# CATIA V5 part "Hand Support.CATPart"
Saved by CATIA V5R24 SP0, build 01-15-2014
Part number: Hand Support
Bounding box of the stored display mesh (mm): x -20 to 20, y -52.995 to 52.995, z -21 to 17
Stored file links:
  C:\Users\minsi\Google 드라이브\CDL_2019\00_CLASS\00_CAD\기말고사\DMU\Hand Support.CATPart
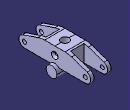
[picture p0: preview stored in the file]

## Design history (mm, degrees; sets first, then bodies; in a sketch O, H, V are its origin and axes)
Body1 (main body)
  Sketch1 on yz-plane, origin (0, 0, 0), H (0, 1, 0), V (0, 0, 1)
    point P1 (0, 17)
    line L1 (0, 17) -> (15.0143, 17)
    point P2 (20, 17)
    line L2 (24.7177, 15.3874) -> (47.5876, 7.57)
    point P3 (47.5876, 7.57)
    arc A1 centre (45, 0) radius 8 from (47.5876, 7.57) to (45, -8) cw
    point P4 (45, 0)
    point P5 (45, -8)
    line L3 (45, -8) -> (0, -8)
    point P6 (0, -8)
    arc A2 centre (15.0143, -13) radius 30 from (15.0143, 17) to (24.7177, 15.3874) cw
    point P7 (15.0143, 17)
    point P8 (24.7177, 15.3874)
    point P10 (0, -8)
    point P11 (-45, -8)
    line L4 (-45, -8) -> (0, -8)
    point P12 (-47.5876, 7.57)
    arc A3 centre (-45, 0) radius 8 from (-47.5876, 7.57) to (-45, -8) ccw
    point P14 (-24.7177, 15.3874)
    line L5 (-24.7177, 15.3874) -> (-47.5876, 7.57)
    point P15 (-15.0143, 17)
    arc A4 centre (-15.0143, -13) radius 30 from (-15.0143, 17) to (-24.7177, 15.3874) ccw
    point P17 (0, 17)
    line L6 (0, 17) -> (-15.0143, 17)
    radius A1 = 8
    distance L1 L3 = 25
    distance P4 V = 45
    distance P2 V = 20
    radius A2 = 30
    coincidence: P1 V, P6 V, P4 H, L1 P2, L2 P2, P1 P17, P6 P10
    horizontal: L1 H, L3 H
    tangency: A1 L2, L3 A1, A2 L1, A2 L2
    symmetry: P6 P10 V, P5 P11 V, L3 L4 V, P3 P12 V, A1 A3 V, P8 P14 V, L2 L5 V, P7 P15 V, A2 A4 V, P1 P17 V, L1 L6 V
  Pad1: profile Sketch1, direction (1, 0, 0), length 15, mirrored extent
  Sketch2 on end face of Pad1, origin (15, 44.3018, -2.6158), H (0, 1, 0), V (0, 0, 1)
    point P1 (0.6982, 2.6158)
    reference projected arc E1 centre (0.6982, 2.6158) radius 8 from (0.6982, -5.3842) to (3.2858, 10.1858) ccw from edge [face of Pad1 from Sketch1.A1 | end face of Pad1]
    concentricity: E1 P1
  Hole1: placed by Sketch2, at (15, 45, 0) direction (-1, 0, 0), diameter 6, through (limit type 3)
  Sketch3 on end face of Pad1, origin (15, -42.3739, 0.0291), H (0, 1, 0), V (0, 0, 1)
    point P1 (-2.6261, -0.0291)
    reference projected arc E1 centre (-2.6261, -0.0291) radius 8 from (-5.2137, 7.5409) to (-2.6261, -8.0291) ccw from edge [face of Pad1 from Sketch1.A3 | end face of Pad1]
    concentricity: E1 P1
  Hole2: placed by Sketch3, at (15, -45, 0) direction (-1, 0, 0), diameter 6, through (limit type 3)
  Sketch4 on yz-plane, origin (0, 0, 0), H (0, 1, 0), V (0, 0, 1)
    circle A1 centre (0, -13) radius 8
    point P1 (0, -13)
    radius A1 = 8
    distance P1 H = 13
    coincidence: P1 V
  Pad2: profile Sketch4, direction (1, 0, 0), length 20, mirrored extent
  Sketch5 on face of Pad1 from Sketch1.L1, origin (-1.3402, 2.5662, 17), H (1, 0, 0), V (0, 1, 0)
    point P1 (1.3402, -2.5662)
    reference intersected line E1 through (1.3402, 0) direction (0, 1) from yz-plane
    reference intersected line E2 through (0, -2.5662) direction (-1, 0) from zx-plane
    coincidence: P1 E1, P1 E2
  Hole3: placed by Sketch5, at (0, 0, 17) direction (0, 0, -1), diameter 12, depth 20
  Sketch6 on end face of Pad1, origin (15, 7.2087, 2.4362), H (0, 1, 0), V (0, 0, 1)
    point P1 (-7.2087, 2.5638)
    reference intersected line E1 through (-7.2087, 0) direction (0, 1) from zx-plane
    reference intersected line E2 through (0, -2.4362) direction (-1, 0) from xy-plane
    distance P1 E2 = 5
    coincidence: P1 E1
  Hole4: placed by Sketch6, at (15, 0, 5) direction (-1, 0, 0), diameter 4, through (limit type 6), countersink depth 3, countersink angle 90
  Mirror1: of Hole4, about yz-plane
  Sketch7 on xy-plane, origin (0, 0, 0), H (1, 0, 0), V (0, 1, 0)
    line L1 (-10, 69.5278) -> (-10, 18)
    line L2 (-10, 18) -> (10, 18)
    line L3 (10, 18) -> (10, 69.5278)
    reference projected line E1 (15, 47.5876) -> (15, 24.7177) from edge [face of Pad1 from Sketch1.L2 | end face of Pad1]
    distance L2 H = 18
    distance L3 E1 = 5
    vertical: L1 V, L3 V
    horizontal: L2 H
    symmetry: L1 L3 V
  Pocket1: profile Sketch7, direction (0, 0, -1), through (limit type 3), opposite side through (limit type 3)
  Mirror2: of Pocket1, about zx-plane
